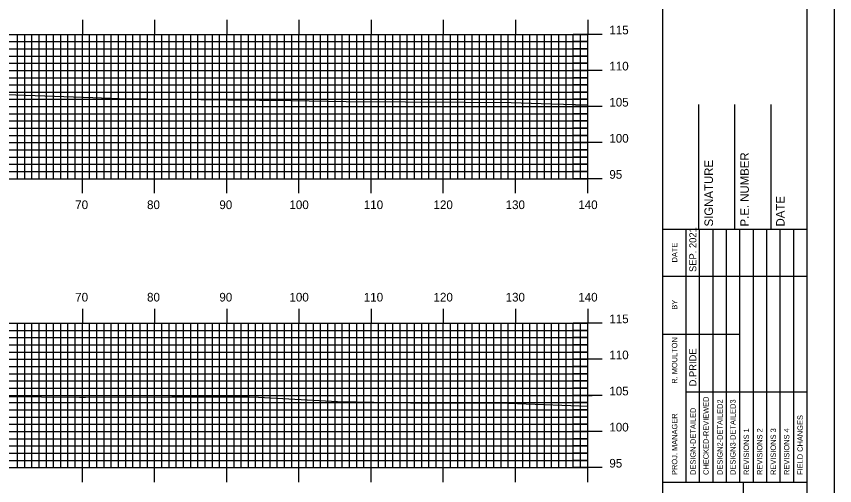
# Model space of a CAD drawing. Extents: x 1779106 to 1779449, y 442591 to 442811.
# Drawn here: x 1779332.2 to 1779445.5, y 442686.2 to 442751.2 of the extents above; entities that cross this region are included whole.
import ezdxf

# ---------------------------------------------------------------- set-up
doc = ezdxf.new("R2010")
doc.units = 0
for name, color, linetype in [('BORDER', 7, 'Continuous'), ('H_V ANNOTATION', 7, 'Continuous'), ('MAJOR', 7, 'Continuous'), ('MINOR', 7, 'Continuous'), ('PLOT BOUNDARY', 7, 'Continuous'), ('S_Roadway_Centerline', 7, 'Continuous')]:
    doc.layers.add(name, color=color, linetype=linetype)

msp = doc.modelspace()

# ---------------------------------------------------------------- linework, layer by layer
at = {"layer": 'BORDER'}
for p, q in [((1779421.73, 442596.67), (1779421.73, 442806.67)), ((1779426.73, 442721.67), (1779426.73, 442738.97)), ((1779431.73, 442721.67), (1779431.73, 442738.97)), ((1779436.73, 442721.67), (1779436.73, 442738.97)), ((1779421.73, 442721.67), (1779441.73, 442721.67)), ((1779421.73, 442686.67), (1779441.73, 442686.67)), ((1779432.91, 442616.67), (1779432.91, 442686.67))]:
    msp.add_line(p, q, dxfattribs=at)
msp.add_lwpolyline([(1779121.73, 442596.67), (1779441.73, 442596.67), (1779441.73, 442806.67), (1779121.73, 442806.67)], close=True, dxfattribs=at)
for points in [[(1779424.96, 442715.17), (1779424.96, 442721.67)], [(1779426.82, 442686.68), (1779426.82, 442721.67)], [(1779428.69, 442721.67), (1779428.69, 442686.68)], [(1779430.55, 442686.68), (1779430.55, 442721.67)], [(1779432.41, 442686.68), (1779432.41, 442721.67)], [(1779434.28, 442686.68), (1779434.28, 442721.67)], [(1779436.14, 442686.68), (1779436.14, 442721.67)], [(1779438, 442686.68), (1779438, 442721.67)], [(1779439.87, 442686.68), (1779439.87, 442721.67)], [(1779424.96, 442686.68), (1779424.96, 442720.26)], [(1779421.73, 442715.17), (1779441.73, 442715.17)], [(1779421.73, 442707.17), (1779424.96, 442707.17)], [(1779424.96, 442707.17), (1779432.41, 442707.17)], [(1779424.96, 442699.17), (1779441.73, 442699.17)]]:
    msp.add_lwpolyline(points, dxfattribs=at)
at = {"layer": 'MAJOR'}
for p, q in [((1779341.33, 442750.67), (1779341.33, 442748.67)), ((1779351.33, 442750.67), (1779351.33, 442748.67)), ((1779361.33, 442750.67), (1779361.33, 442748.67)), ((1779371.33, 442750.67), (1779371.33, 442748.67)), ((1779381.33, 442750.67), (1779381.33, 442748.67)), ((1779391.33, 442750.67), (1779391.33, 442748.67)), ((1779401.33, 442750.67), (1779401.33, 442748.67)), ((1779411.33, 442750.67), (1779411.33, 442748.67)), ((1779131.33, 442748.67), (1779411.33, 442748.67)), ((1779131.33, 442748.67), (1779411.33, 442748.67)), ((1779341.33, 442728.67), (1779341.33, 442748.67)), ((1779351.33, 442728.67), (1779351.33, 442748.67)), ((1779361.33, 442728.67), (1779361.33, 442748.67)), ((1779371.33, 442728.67), (1779371.33, 442748.67)), ((1779381.33, 442728.67), (1779381.33, 442748.67)), ((1779391.33, 442728.67), (1779391.33, 442748.67)), ((1779401.33, 442728.67), (1779401.33, 442748.67)), ((1779413.33, 442748.67), (1779409.33, 442748.67)), ((1779411.33, 442728.67), (1779411.33, 442748.67)), ((1779411.33, 442728.67), (1779411.33, 442748.67)), ((1779131.33, 442743.67), (1779411.33, 442743.67)), ((1779413.33, 442743.67), (1779409.33, 442743.67)), ((1779131.33, 442738.67), (1779411.33, 442738.67)), ((1779413.33, 442738.67), (1779409.33, 442738.67)), ((1779131.33, 442733.67), (1779411.33, 442733.67)), ((1779413.33, 442733.67), (1779409.33, 442733.67)), ((1779131.33, 442728.67), (1779411.33, 442728.67)), ((1779131.33, 442728.67), (1779411.33, 442728.67)), ((1779341.33, 442726.66), (1779341.33, 442728.67)), ((1779351.33, 442726.66), (1779351.33, 442728.67)), ((1779361.33, 442726.66), (1779361.33, 442728.67)), ((1779371.33, 442726.66), (1779371.33, 442728.67)), ((1779381.33, 442726.66), (1779381.33, 442728.67)), ((1779391.33, 442726.66), (1779391.33, 442728.67)), ((1779401.33, 442726.66), (1779401.33, 442728.67)), ((1779413.33, 442728.67), (1779409.33, 442728.67)), ((1779411.33, 442726.66), (1779411.33, 442728.67)), ((1779341.33, 442710.67), (1779341.33, 442708.67)), ((1779351.33, 442710.67), (1779351.33, 442708.67)), ((1779361.33, 442710.67), (1779361.33, 442708.67)), ((1779371.33, 442710.67), (1779371.33, 442708.67)), ((1779381.33, 442710.67), (1779381.33, 442708.67)), ((1779391.33, 442710.67), (1779391.33, 442708.67)), ((1779401.33, 442710.67), (1779401.33, 442708.67)), ((1779411.33, 442710.67), (1779411.33, 442708.67)), ((1779131.33, 442708.67), (1779411.33, 442708.67)), ((1779131.33, 442708.67), (1779411.33, 442708.67)), ((1779341.33, 442688.67), (1779341.33, 442708.67)), ((1779351.33, 442688.67), (1779351.33, 442708.67)), ((1779361.33, 442688.67), (1779361.33, 442708.67)), ((1779371.33, 442688.67), (1779371.33, 442708.67)), ((1779381.33, 442688.67), (1779381.33, 442708.67)), ((1779391.33, 442688.67), (1779391.33, 442708.67)), ((1779401.33, 442688.67), (1779401.33, 442708.67)), ((1779413.33, 442708.67), (1779409.33, 442708.67)), ((1779411.33, 442688.67), (1779411.33, 442708.67)), ((1779411.33, 442688.67), (1779411.33, 442708.67)), ((1779131.33, 442703.67), (1779411.33, 442703.67)), ((1779413.33, 442703.67), (1779409.33, 442703.67)), ((1779131.96, 442698.67), (1779411.96, 442698.67)), ((1779413.33, 442698.67), (1779409.33, 442698.67)), ((1779131.33, 442693.67), (1779411.33, 442693.67)), ((1779413.33, 442693.67), (1779409.33, 442693.67)), ((1779131.33, 442688.67), (1779411.33, 442688.67)), ((1779131.33, 442688.67), (1779411.33, 442688.67)), ((1779341.33, 442686.66), (1779341.33, 442688.67)), ((1779351.33, 442686.66), (1779351.33, 442688.67)), ((1779361.33, 442686.66), (1779361.33, 442688.67)), ((1779371.33, 442686.66), (1779371.33, 442688.67)), ((1779381.33, 442686.66), (1779381.33, 442688.67)), ((1779391.33, 442686.66), (1779391.33, 442688.67)), ((1779401.33, 442686.66), (1779401.33, 442688.67)), ((1779413.33, 442688.67), (1779409.33, 442688.67)), ((1779411.33, 442686.66), (1779411.33, 442688.67))]:
    msp.add_line(p, q, dxfattribs=at)
at = {"layer": 'MINOR'}
for p, q in [((1779332.33, 442728.67), (1779332.33, 442748.67)), ((1779333.33, 442728.67), (1779333.33, 442748.67)), ((1779334.33, 442728.67), (1779334.33, 442748.67)), ((1779335.33, 442728.67), (1779335.33, 442748.67)), ((1779336.33, 442728.67), (1779336.33, 442748.67)), ((1779337.33, 442728.67), (1779337.33, 442748.67)), ((1779338.33, 442728.67), (1779338.33, 442748.67)), ((1779339.33, 442728.67), (1779339.33, 442748.67)), ((1779340.33, 442728.67), (1779340.33, 442748.67)), ((1779342.33, 442728.67), (1779342.33, 442748.67)), ((1779343.33, 442728.67), (1779343.33, 442748.67)), ((1779344.33, 442728.67), (1779344.33, 442748.67)), ((1779345.33, 442728.67), (1779345.33, 442748.67)), ((1779346.33, 442728.67), (1779346.33, 442748.67)), ((1779347.33, 442728.67), (1779347.33, 442748.67)), ((1779348.33, 442728.67), (1779348.33, 442748.67)), ((1779349.33, 442728.67), (1779349.33, 442748.67)), ((1779350.33, 442728.67), (1779350.33, 442748.67)), ((1779352.33, 442728.67), (1779352.33, 442748.67)), ((1779353.33, 442728.67), (1779353.33, 442748.67)), ((1779354.33, 442728.67), (1779354.33, 442748.67)), ((1779355.33, 442728.67), (1779355.33, 442748.67)), ((1779356.33, 442728.67), (1779356.33, 442748.67)), ((1779357.33, 442728.67), (1779357.33, 442748.67)), ((1779358.33, 442728.67), (1779358.33, 442748.67)), ((1779359.33, 442728.67), (1779359.33, 442748.67)), ((1779360.33, 442728.67), (1779360.33, 442748.67)), ((1779362.33, 442728.67), (1779362.33, 442748.67)), ((1779363.33, 442728.67), (1779363.33, 442748.67)), ((1779364.33, 442728.67), (1779364.33, 442748.67)), ((1779365.33, 442728.67), (1779365.33, 442748.67)), ((1779366.33, 442728.67), (1779366.33, 442748.67)), ((1779367.33, 442728.67), (1779367.33, 442748.67)), ((1779368.33, 442728.67), (1779368.33, 442748.67)), ((1779369.33, 442728.67), (1779369.33, 442748.67)), ((1779370.33, 442728.67), (1779370.33, 442748.67)), ((1779372.33, 442728.67), (1779372.33, 442748.67)), ((1779373.33, 442728.67), (1779373.33, 442748.67)), ((1779374.33, 442728.67), (1779374.33, 442748.67)), ((1779375.33, 442728.67), (1779375.33, 442748.67)), ((1779376.33, 442728.67), (1779376.33, 442748.67)), ((1779377.33, 442728.67), (1779377.33, 442748.67)), ((1779378.33, 442728.67), (1779378.33, 442748.67)), ((1779379.33, 442728.67), (1779379.33, 442748.67)), ((1779380.33, 442728.67), (1779380.33, 442748.67)), ((1779382.33, 442728.67), (1779382.33, 442748.67)), ((1779383.33, 442728.67), (1779383.33, 442748.67)), ((1779384.33, 442728.67), (1779384.33, 442748.67)), ((1779385.33, 442728.67), (1779385.33, 442748.67)), ((1779386.33, 442728.67), (1779386.33, 442748.67)), ((1779387.33, 442728.67), (1779387.33, 442748.67)), ((1779388.33, 442728.67), (1779388.33, 442748.67)), ((1779389.33, 442728.67), (1779389.33, 442748.67)), ((1779390.33, 442728.67), (1779390.33, 442748.67)), ((1779392.33, 442728.67), (1779392.33, 442748.67)), ((1779393.33, 442728.67), (1779393.33, 442748.67)), ((1779394.33, 442728.67), (1779394.33, 442748.67)), ((1779395.33, 442728.67), (1779395.33, 442748.67)), ((1779396.33, 442728.67), (1779396.33, 442748.67)), ((1779397.33, 442728.67), (1779397.33, 442748.67)), ((1779398.33, 442728.67), (1779398.33, 442748.67)), ((1779399.33, 442728.67), (1779399.33, 442748.67)), ((1779400.33, 442728.67), (1779400.33, 442748.67)), ((1779402.33, 442728.67), (1779402.33, 442748.67)), ((1779403.33, 442728.67), (1779403.33, 442748.67)), ((1779404.33, 442728.67), (1779404.33, 442748.67)), ((1779405.33, 442728.67), (1779405.33, 442748.67)), ((1779406.33, 442728.67), (1779406.33, 442748.67)), ((1779407.33, 442728.67), (1779407.33, 442748.67)), ((1779408.33, 442728.67), (1779408.33, 442748.67)), ((1779409.33, 442728.67), (1779409.33, 442748.67)), ((1779410.33, 442728.67), (1779410.33, 442748.67)), ((1779131.33, 442747.67), (1779411.33, 442747.67)), ((1779131.33, 442746.67), (1779411.33, 442746.67)), ((1779411.33, 442747.67), (1779409.33, 442747.67)), ((1779411.33, 442746.67), (1779409.33, 442746.67)), ((1779131.33, 442745.67), (1779411.33, 442745.67)), ((1779411.33, 442745.67), (1779409.33, 442745.67)), ((1779131.33, 442744.67), (1779411.33, 442744.67)), ((1779411.33, 442744.67), (1779409.33, 442744.67)), ((1779131.33, 442742.67), (1779411.33, 442742.67)), ((1779411.33, 442742.67), (1779409.33, 442742.67)), ((1779131.33, 442741.67), (1779411.33, 442741.67)), ((1779411.33, 442741.67), (1779409.33, 442741.67)), ((1779131.33, 442740.67), (1779411.33, 442740.67)), ((1779411.33, 442740.67), (1779409.33, 442740.67)), ((1779131.33, 442739.67), (1779411.33, 442739.67)), ((1779411.33, 442739.67), (1779409.33, 442739.67)), ((1779131.33, 442737.67), (1779411.33, 442737.67)), ((1779411.33, 442737.67), (1779409.33, 442737.67)), ((1779131.33, 442736.67), (1779411.33, 442736.67)), ((1779411.33, 442736.67), (1779409.33, 442736.67)), ((1779131.33, 442735.67), (1779411.33, 442735.67)), ((1779411.33, 442735.67), (1779409.33, 442735.67)), ((1779131.33, 442734.67), (1779411.33, 442734.67)), ((1779411.33, 442734.67), (1779409.33, 442734.67)), ((1779131.33, 442732.67), (1779411.33, 442732.67)), ((1779411.33, 442732.67), (1779409.33, 442732.67)), ((1779131.33, 442731.67), (1779411.33, 442731.67)), ((1779411.33, 442731.67), (1779409.33, 442731.67)), ((1779131.33, 442730.67), (1779411.33, 442730.67)), ((1779131.33, 442729.67), (1779411.33, 442729.67)), ((1779411.33, 442730.67), (1779409.33, 442730.67)), ((1779411.33, 442729.67), (1779409.33, 442729.67)), ((1779332.33, 442688.67), (1779332.33, 442708.67)), ((1779333.33, 442688.67), (1779333.33, 442708.67)), ((1779334.33, 442688.67), (1779334.33, 442708.67)), ((1779335.33, 442688.67), (1779335.33, 442708.67)), ((1779336.33, 442688.67), (1779336.33, 442708.67)), ((1779337.33, 442688.67), (1779337.33, 442708.67)), ((1779338.33, 442688.67), (1779338.33, 442708.67)), ((1779339.33, 442688.67), (1779339.33, 442708.67)), ((1779340.33, 442688.67), (1779340.33, 442708.67)), ((1779342.33, 442688.67), (1779342.33, 442708.67)), ((1779343.33, 442688.67), (1779343.33, 442708.67)), ((1779344.33, 442688.67), (1779344.33, 442708.67)), ((1779345.33, 442688.67), (1779345.33, 442708.67)), ((1779346.33, 442688.67), (1779346.33, 442708.67)), ((1779347.33, 442688.67), (1779347.33, 442708.67)), ((1779348.33, 442688.67), (1779348.33, 442708.67)), ((1779349.33, 442688.67), (1779349.33, 442708.67)), ((1779350.33, 442688.67), (1779350.33, 442708.67)), ((1779352.33, 442688.67), (1779352.33, 442708.67)), ((1779353.33, 442688.67), (1779353.33, 442708.67)), ((1779354.33, 442688.67), (1779354.33, 442708.67)), ((1779355.33, 442688.67), (1779355.33, 442708.67)), ((1779356.33, 442688.67), (1779356.33, 442708.67)), ((1779357.33, 442688.67), (1779357.33, 442708.67)), ((1779358.33, 442688.67), (1779358.33, 442708.67)), ((1779359.33, 442688.67), (1779359.33, 442708.67)), ((1779360.33, 442688.67), (1779360.33, 442708.67)), ((1779362.33, 442688.67), (1779362.33, 442708.67)), ((1779363.33, 442688.67), (1779363.33, 442708.67)), ((1779364.33, 442688.67), (1779364.33, 442708.67)), ((1779365.33, 442688.67), (1779365.33, 442708.67)), ((1779366.33, 442688.67), (1779366.33, 442708.67)), ((1779367.33, 442688.67), (1779367.33, 442708.67)), ((1779368.33, 442688.67), (1779368.33, 442708.67)), ((1779369.33, 442688.67), (1779369.33, 442708.67)), ((1779370.33, 442688.67), (1779370.33, 442708.67)), ((1779372.33, 442688.67), (1779372.33, 442708.67)), ((1779373.33, 442688.67), (1779373.33, 442708.67)), ((1779374.33, 442688.67), (1779374.33, 442708.67)), ((1779375.33, 442688.67), (1779375.33, 442708.67)), ((1779376.33, 442688.67), (1779376.33, 442708.67)), ((1779377.33, 442688.67), (1779377.33, 442708.67)), ((1779378.33, 442688.67), (1779378.33, 442708.67)), ((1779379.33, 442688.67), (1779379.33, 442708.67)), ((1779380.33, 442688.67), (1779380.33, 442708.67)), ((1779382.33, 442688.67), (1779382.33, 442708.67)), ((1779383.33, 442688.67), (1779383.33, 442708.67)), ((1779384.33, 442688.67), (1779384.33, 442708.67)), ((1779385.33, 442688.67), (1779385.33, 442708.67)), ((1779386.33, 442688.67), (1779386.33, 442708.67)), ((1779387.33, 442688.67), (1779387.33, 442708.67)), ((1779388.33, 442688.67), (1779388.33, 442708.67)), ((1779389.33, 442688.67), (1779389.33, 442708.67)), ((1779390.33, 442688.67), (1779390.33, 442708.67)), ((1779392.33, 442688.67), (1779392.33, 442708.67)), ((1779393.33, 442688.67), (1779393.33, 442708.67)), ((1779394.33, 442688.67), (1779394.33, 442708.67)), ((1779395.33, 442688.67), (1779395.33, 442708.67)), ((1779396.33, 442688.67), (1779396.33, 442708.67)), ((1779397.33, 442688.67), (1779397.33, 442708.67)), ((1779398.33, 442688.67), (1779398.33, 442708.67)), ((1779399.33, 442688.67), (1779399.33, 442708.67)), ((1779400.33, 442688.67), (1779400.33, 442708.67)), ((1779402.33, 442688.67), (1779402.33, 442708.67)), ((1779403.33, 442688.67), (1779403.33, 442708.67)), ((1779404.33, 442688.67), (1779404.33, 442708.67)), ((1779405.33, 442688.67), (1779405.33, 442708.67)), ((1779406.33, 442688.67), (1779406.33, 442708.67)), ((1779407.33, 442688.67), (1779407.33, 442708.67)), ((1779408.33, 442688.67), (1779408.33, 442708.67)), ((1779409.33, 442688.67), (1779409.33, 442708.67)), ((1779410.33, 442688.67), (1779410.33, 442708.67)), ((1779131.33, 442707.67), (1779411.33, 442707.67)), ((1779411.33, 442707.67), (1779409.33, 442707.67)), ((1779131.33, 442706.67), (1779411.33, 442706.67)), ((1779411.33, 442706.67), (1779409.33, 442706.67)), ((1779131.33, 442705.67), (1779411.33, 442705.67)), ((1779131.33, 442704.67), (1779411.33, 442704.67)), ((1779411.33, 442705.67), (1779409.33, 442705.67)), ((1779411.33, 442704.67), (1779409.33, 442704.67)), ((1779131.33, 442702.67), (1779411.33, 442702.67)), ((1779411.33, 442702.67), (1779409.33, 442702.67)), ((1779131.33, 442701.67), (1779411.33, 442701.67)), ((1779411.33, 442701.67), (1779409.33, 442701.67)), ((1779131.33, 442700.67), (1779411.33, 442700.67)), ((1779411.33, 442700.67), (1779409.33, 442700.67)), ((1779131.33, 442699.67), (1779411.33, 442699.67)), ((1779411.33, 442699.67), (1779409.33, 442699.67)), ((1779131.33, 442697.67), (1779411.33, 442697.67)), ((1779411.33, 442697.67), (1779409.33, 442697.67)), ((1779131.33, 442696.67), (1779411.33, 442696.67)), ((1779131.33, 442695.67), (1779411.33, 442695.67)), ((1779411.33, 442696.67), (1779409.33, 442696.67)), ((1779411.33, 442695.67), (1779409.33, 442695.67)), ((1779131.33, 442694.67), (1779411.33, 442694.67)), ((1779411.33, 442694.67), (1779409.33, 442694.67)), ((1779131.33, 442692.67), (1779411.33, 442692.67)), ((1779411.33, 442692.67), (1779409.33, 442692.67)), ((1779131.33, 442691.67), (1779411.33, 442691.67)), ((1779411.33, 442691.67), (1779409.33, 442691.67)), ((1779131.33, 442690.67), (1779411.33, 442690.67)), ((1779411.33, 442690.67), (1779409.33, 442690.67)), ((1779131.33, 442689.67), (1779411.33, 442689.67)), ((1779411.33, 442689.67), (1779409.33, 442689.67))]:
    msp.add_line(p, q, dxfattribs=at)
at = {"layer": 'PLOT BOUNDARY'}
msp.add_lwpolyline([(1779105.54, 442590.55), (1779445.54, 442590.55), (1779445.54, 442810.55), (1779105.54, 442810.55)], close=True, dxfattribs=at)
at = {"layer": 'S_Roadway_Centerline'}
for points in [[(1779322.75, 442740.62), (1779342.78, 442739.92), (1779346.4, 442739.77), (1779361.54, 442739.61), (1779370.19, 442739.49), (1779377.86, 442739.37), (1779394.29, 442739.27), (1779400.75, 442739.24), (1779406.28, 442739.04), (1779411.33, 442738.92)], [(1779319.86, 442698.59), (1779340.93, 442698.43), (1779341.69, 442698.42), (1779341.72, 442698.42), (1779341.74, 442698.42), (1779353.71, 442698.46), (1779364.43, 442698.45), (1779365.71, 442698.42), (1779376.65, 442697.81), (1779386.76, 442697.63), (1779390.12, 442697.62), (1779399.09, 442697.64), (1779408.98, 442697.29), (1779411.33, 442697.19)]]:
    msp.add_lwpolyline(points, dxfattribs=at)

# ---------------------------------------------------------------- texts
at = {"layer": 'BORDER'}
for s, height, p in [('P.E. NUMBER', 1.1811, (1779433.65, 442722.06)), ('SIGNATURE', 1.181, (1779428.69, 442722.06)), ('DATE', 1.181, (1779438.61, 442722.06)), ('SEP. 2021', 0.969, (1779426.38, 442715.76)), ('DATE', 0.743, (1779423.74, 442717.08)), ('BY', 0.743, (1779423.74, 442710.54)), ('R. MOULTON', 0.745, (1779423.74, 442700.28)), ('D.PRIDE', 0.969, (1779426.38, 442699.92)), ('CHECKED-REVIEWED', 0.7455, (1779428.09, 442687.65)), ('DESIGN2-DETAILED2', 0.7455, (1779430.03, 442687.65)), ('DESIGN3-DETAILED3', 0.7455, (1779431.82, 442687.65)), ('PROJ. MANAGER', 0.7455, (1779423.74, 442687.65)), ('DESIGN-DETAILED', 0.7455, (1779426.3, 442687.65)), ('FIELD CHANGES', 0.7455, (1779441.13, 442687.65)), ('REVISIONS 1', 0.7455, (1779433.68, 442687.65)), ('REVISIONS 2', 0.7455, (1779435.54, 442687.65)), ('REVISIONS 3', 0.7455, (1779437.41, 442687.65)), ('REVISIONS 4', 0.7455, (1779439.27, 442687.65))]:
    msp.add_text(s, height=height, rotation=90, dxfattribs=at).set_placement(p)
at = {"layer": 'H_V ANNOTATION'}
for s, p in [('115', (1779414.33, 442748.67)), ('110', (1779414.33, 442743.67)), ('105', (1779414.33, 442738.67)), ('100', (1779414.33, 442733.67)), ('95', (1779414.33, 442728.67)), ('70', (1779340.33, 442724.47)), ('80', (1779350.28, 442724.47)), ('90', (1779360.3, 442724.47)), ('100', (1779370.01, 442724.47)), ('110', (1779380.31, 442724.47)), ('120', (1779389.97, 442724.47)), ('130', (1779399.96, 442724.47)), ('140', (1779410.03, 442724.47)), ('70', (1779340.33, 442711.67)), ('80', (1779350.28, 442711.67)), ('90', (1779360.3, 442711.67)), ('100', (1779370.01, 442711.67)), ('110', (1779380.31, 442711.67)), ('120', (1779389.97, 442711.67)), ('130', (1779399.96, 442711.67)), ('140', (1779410.03, 442711.67)), ('115', (1779414.33, 442708.67)), ('110', (1779414.33, 442703.67)), ('105', (1779414.33, 442698.67)), ('100', (1779414.33, 442693.67)), ('95', (1779414.33, 442688.67))]:
    msp.add_text(s, height=1.2, dxfattribs=at).set_placement(p)

doc.saveas('drawing.dxf')
